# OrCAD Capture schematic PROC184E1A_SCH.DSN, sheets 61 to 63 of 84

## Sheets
61 64. DSI to eDP bridge: size C; title: DSI TO EDP BRIDGE; note: PROC184_SCH
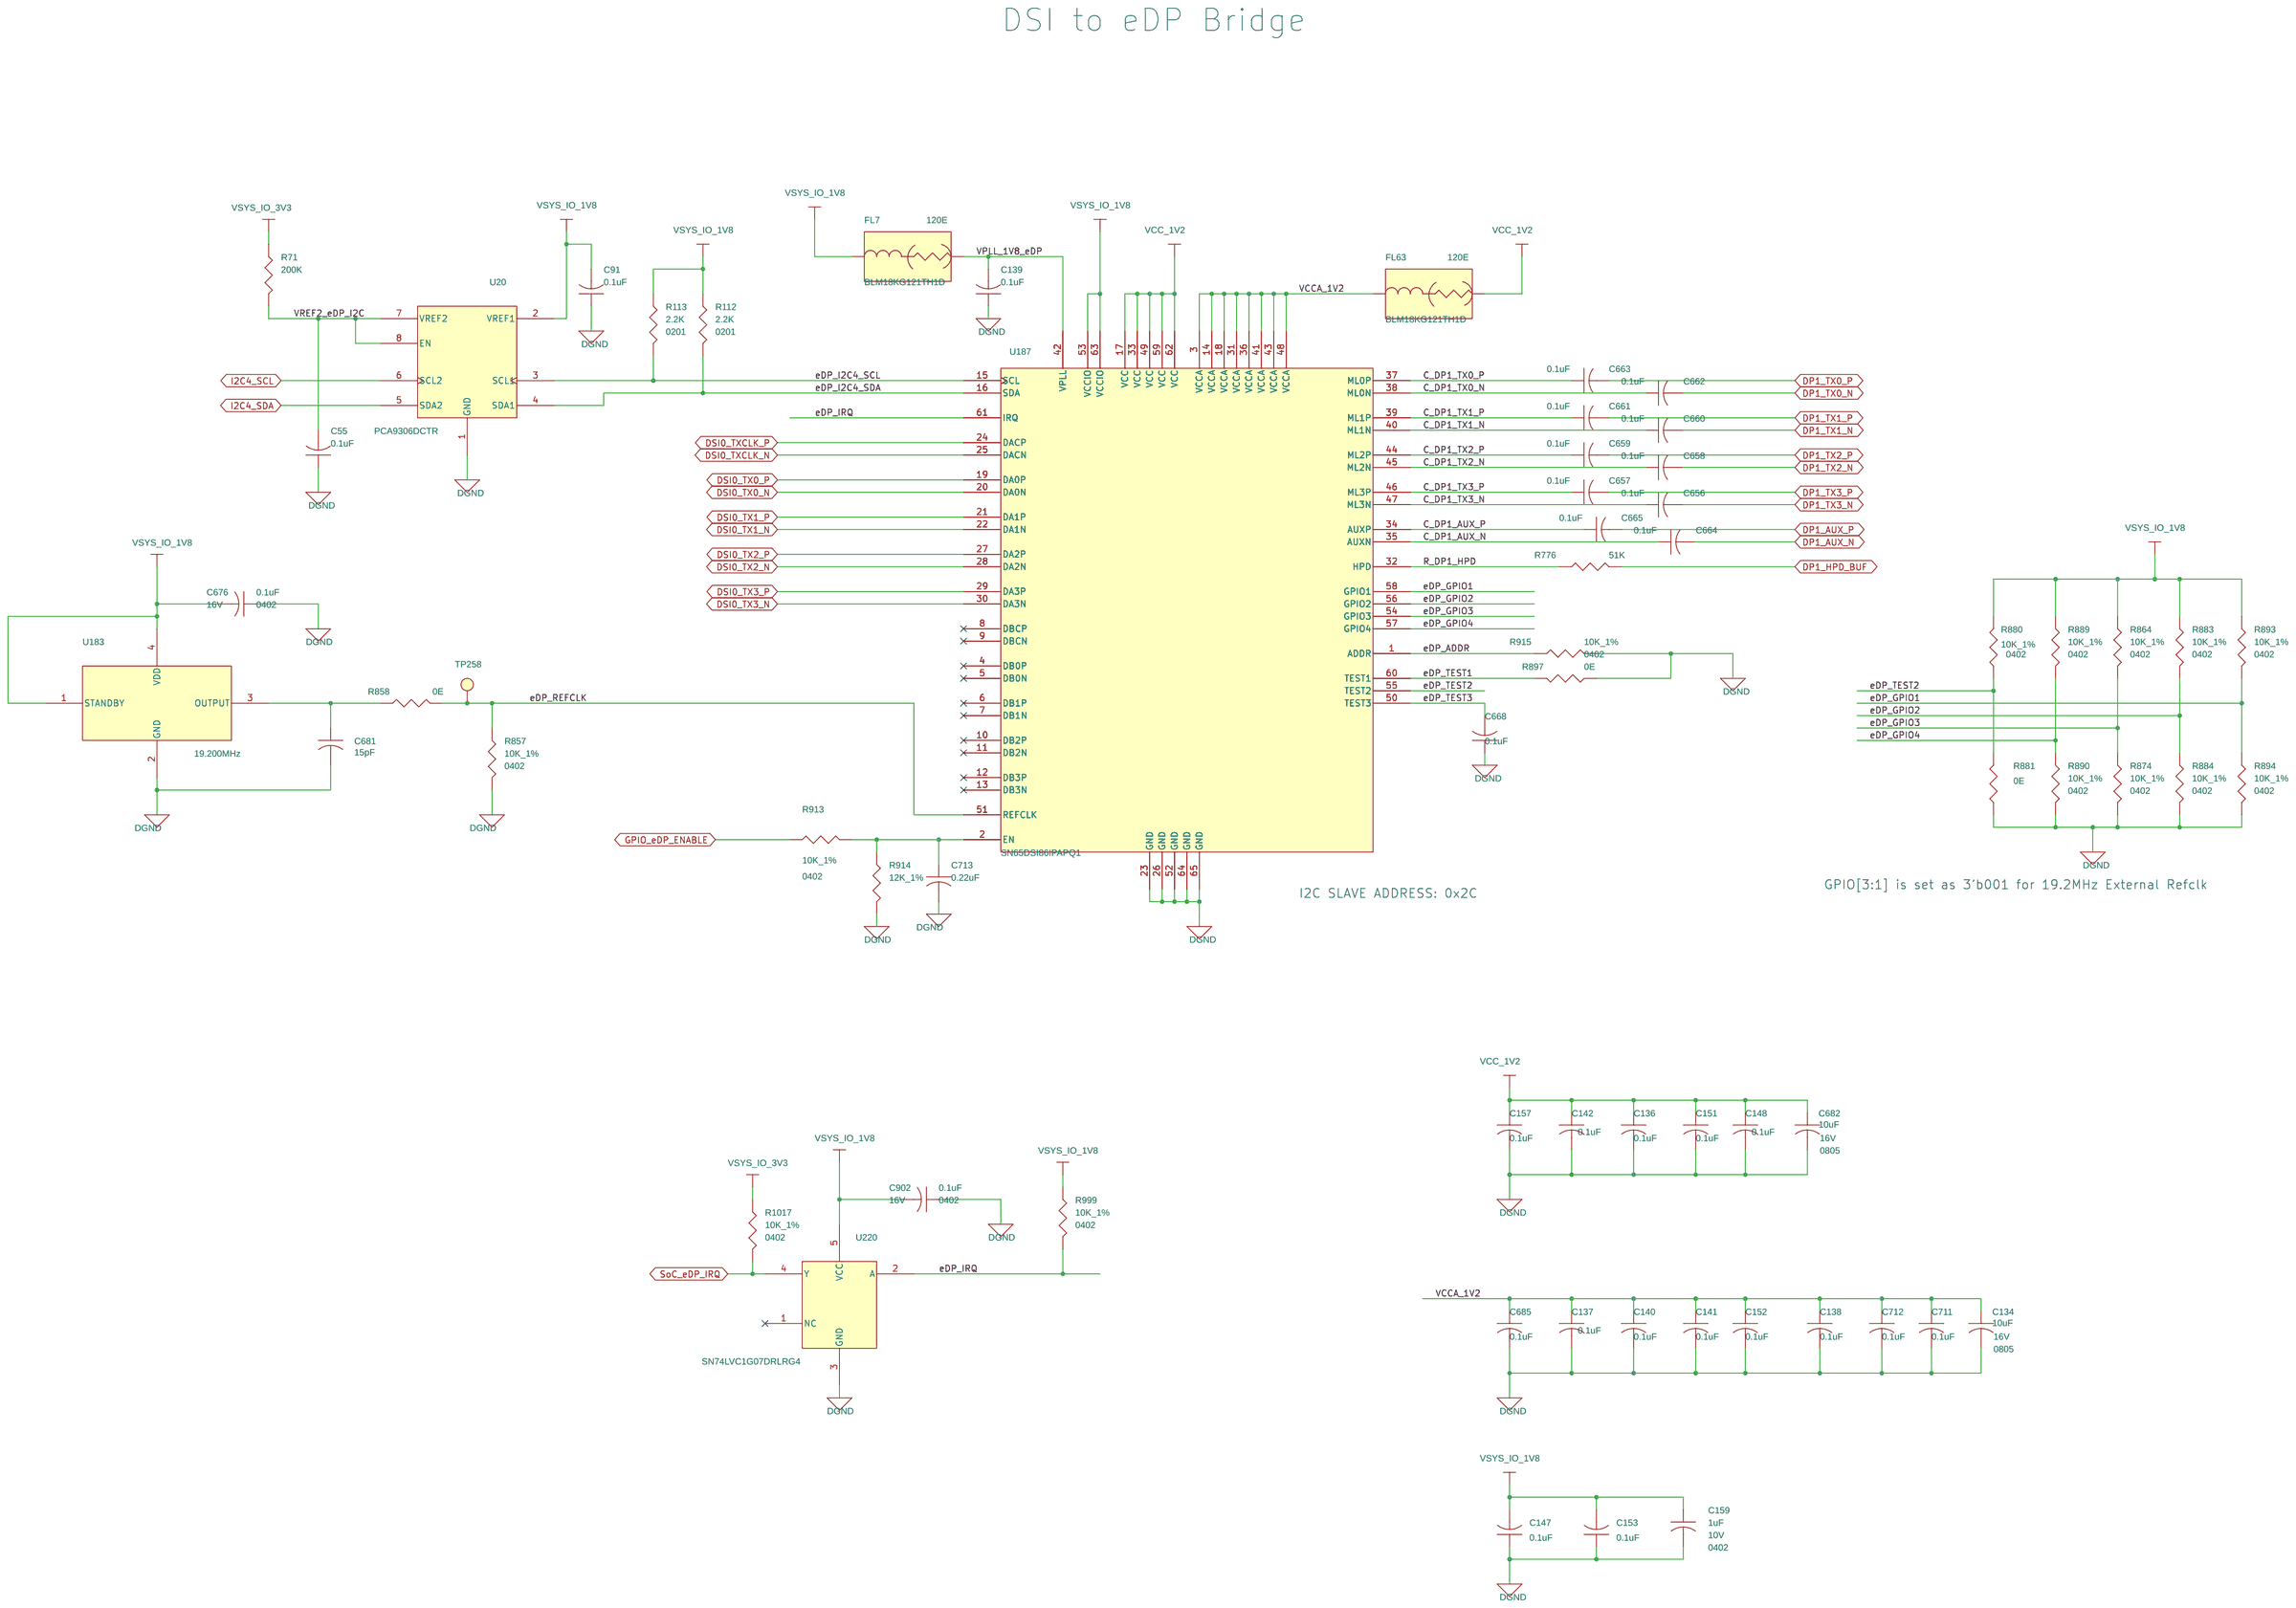
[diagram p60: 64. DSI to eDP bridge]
62 69. BOOT MODE BUFFER & SWITCHES: size C; title: BOOT MODE BUFFER & SWITCHES; note: PROC184_SCH
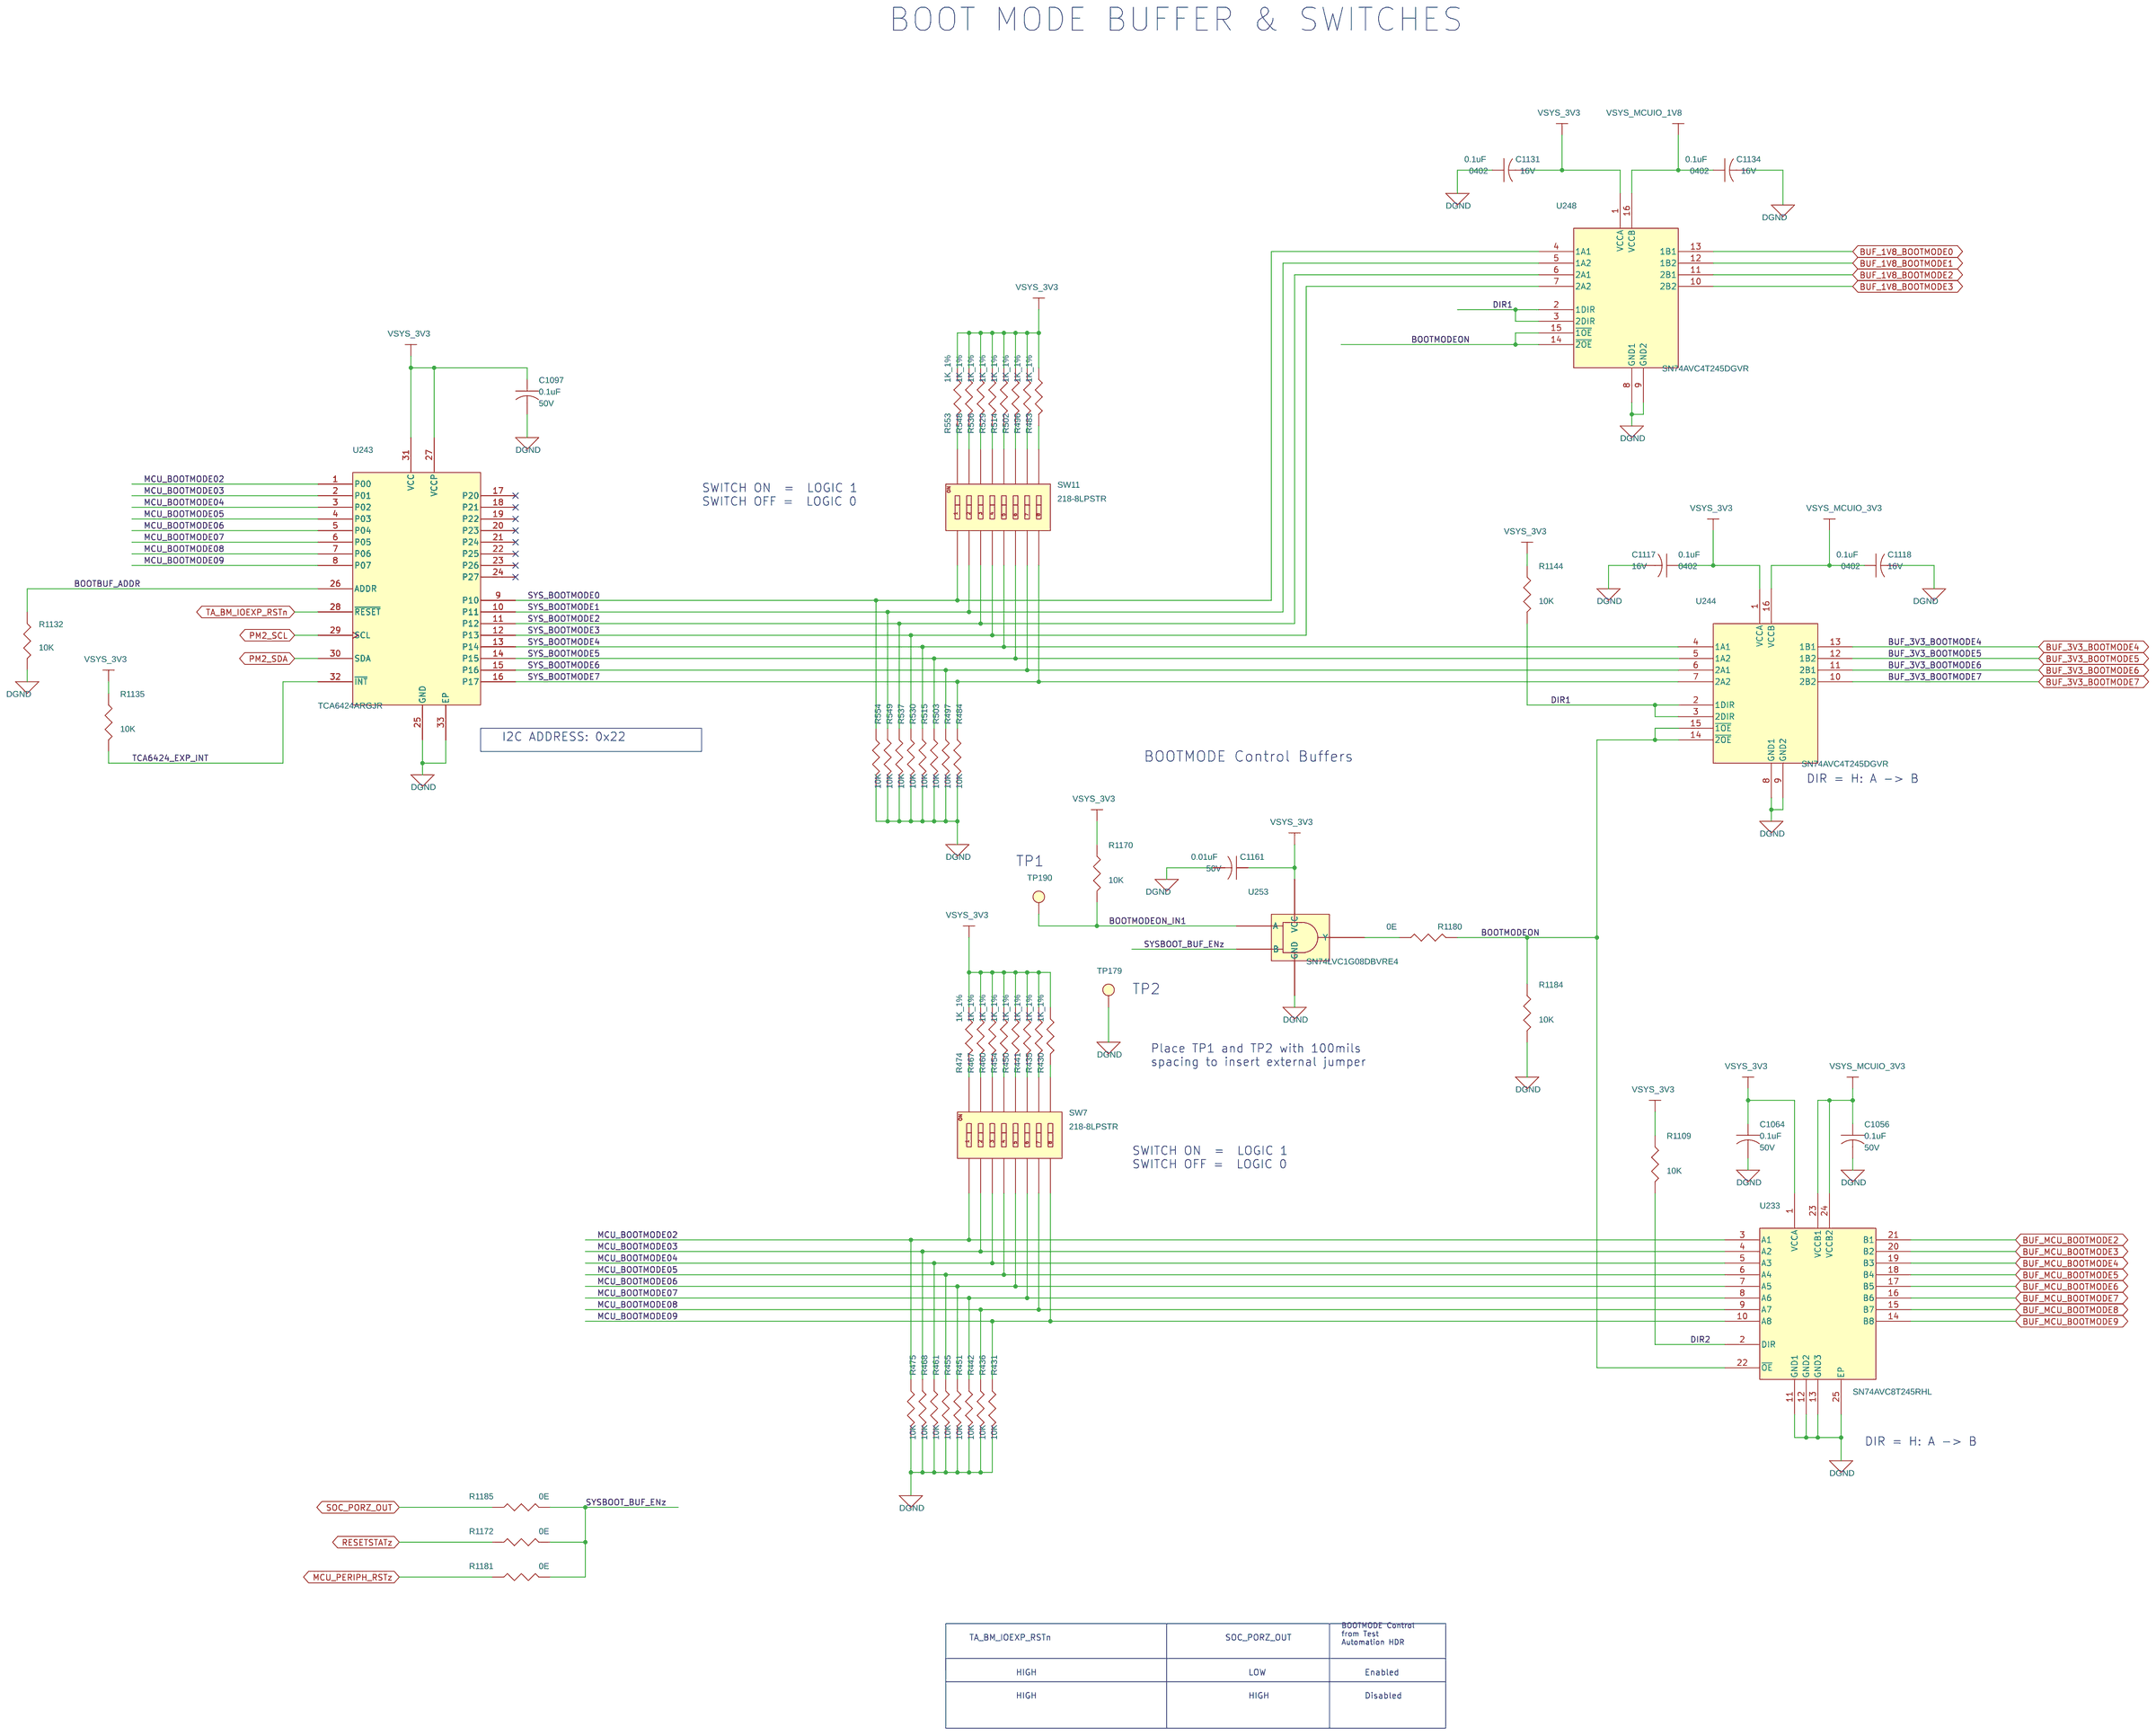
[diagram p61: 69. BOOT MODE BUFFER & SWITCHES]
63 70. TEST AUTOMATION HEADER: size C; title: TEST AUTOMATION HEADER; note: PROC184_SCH
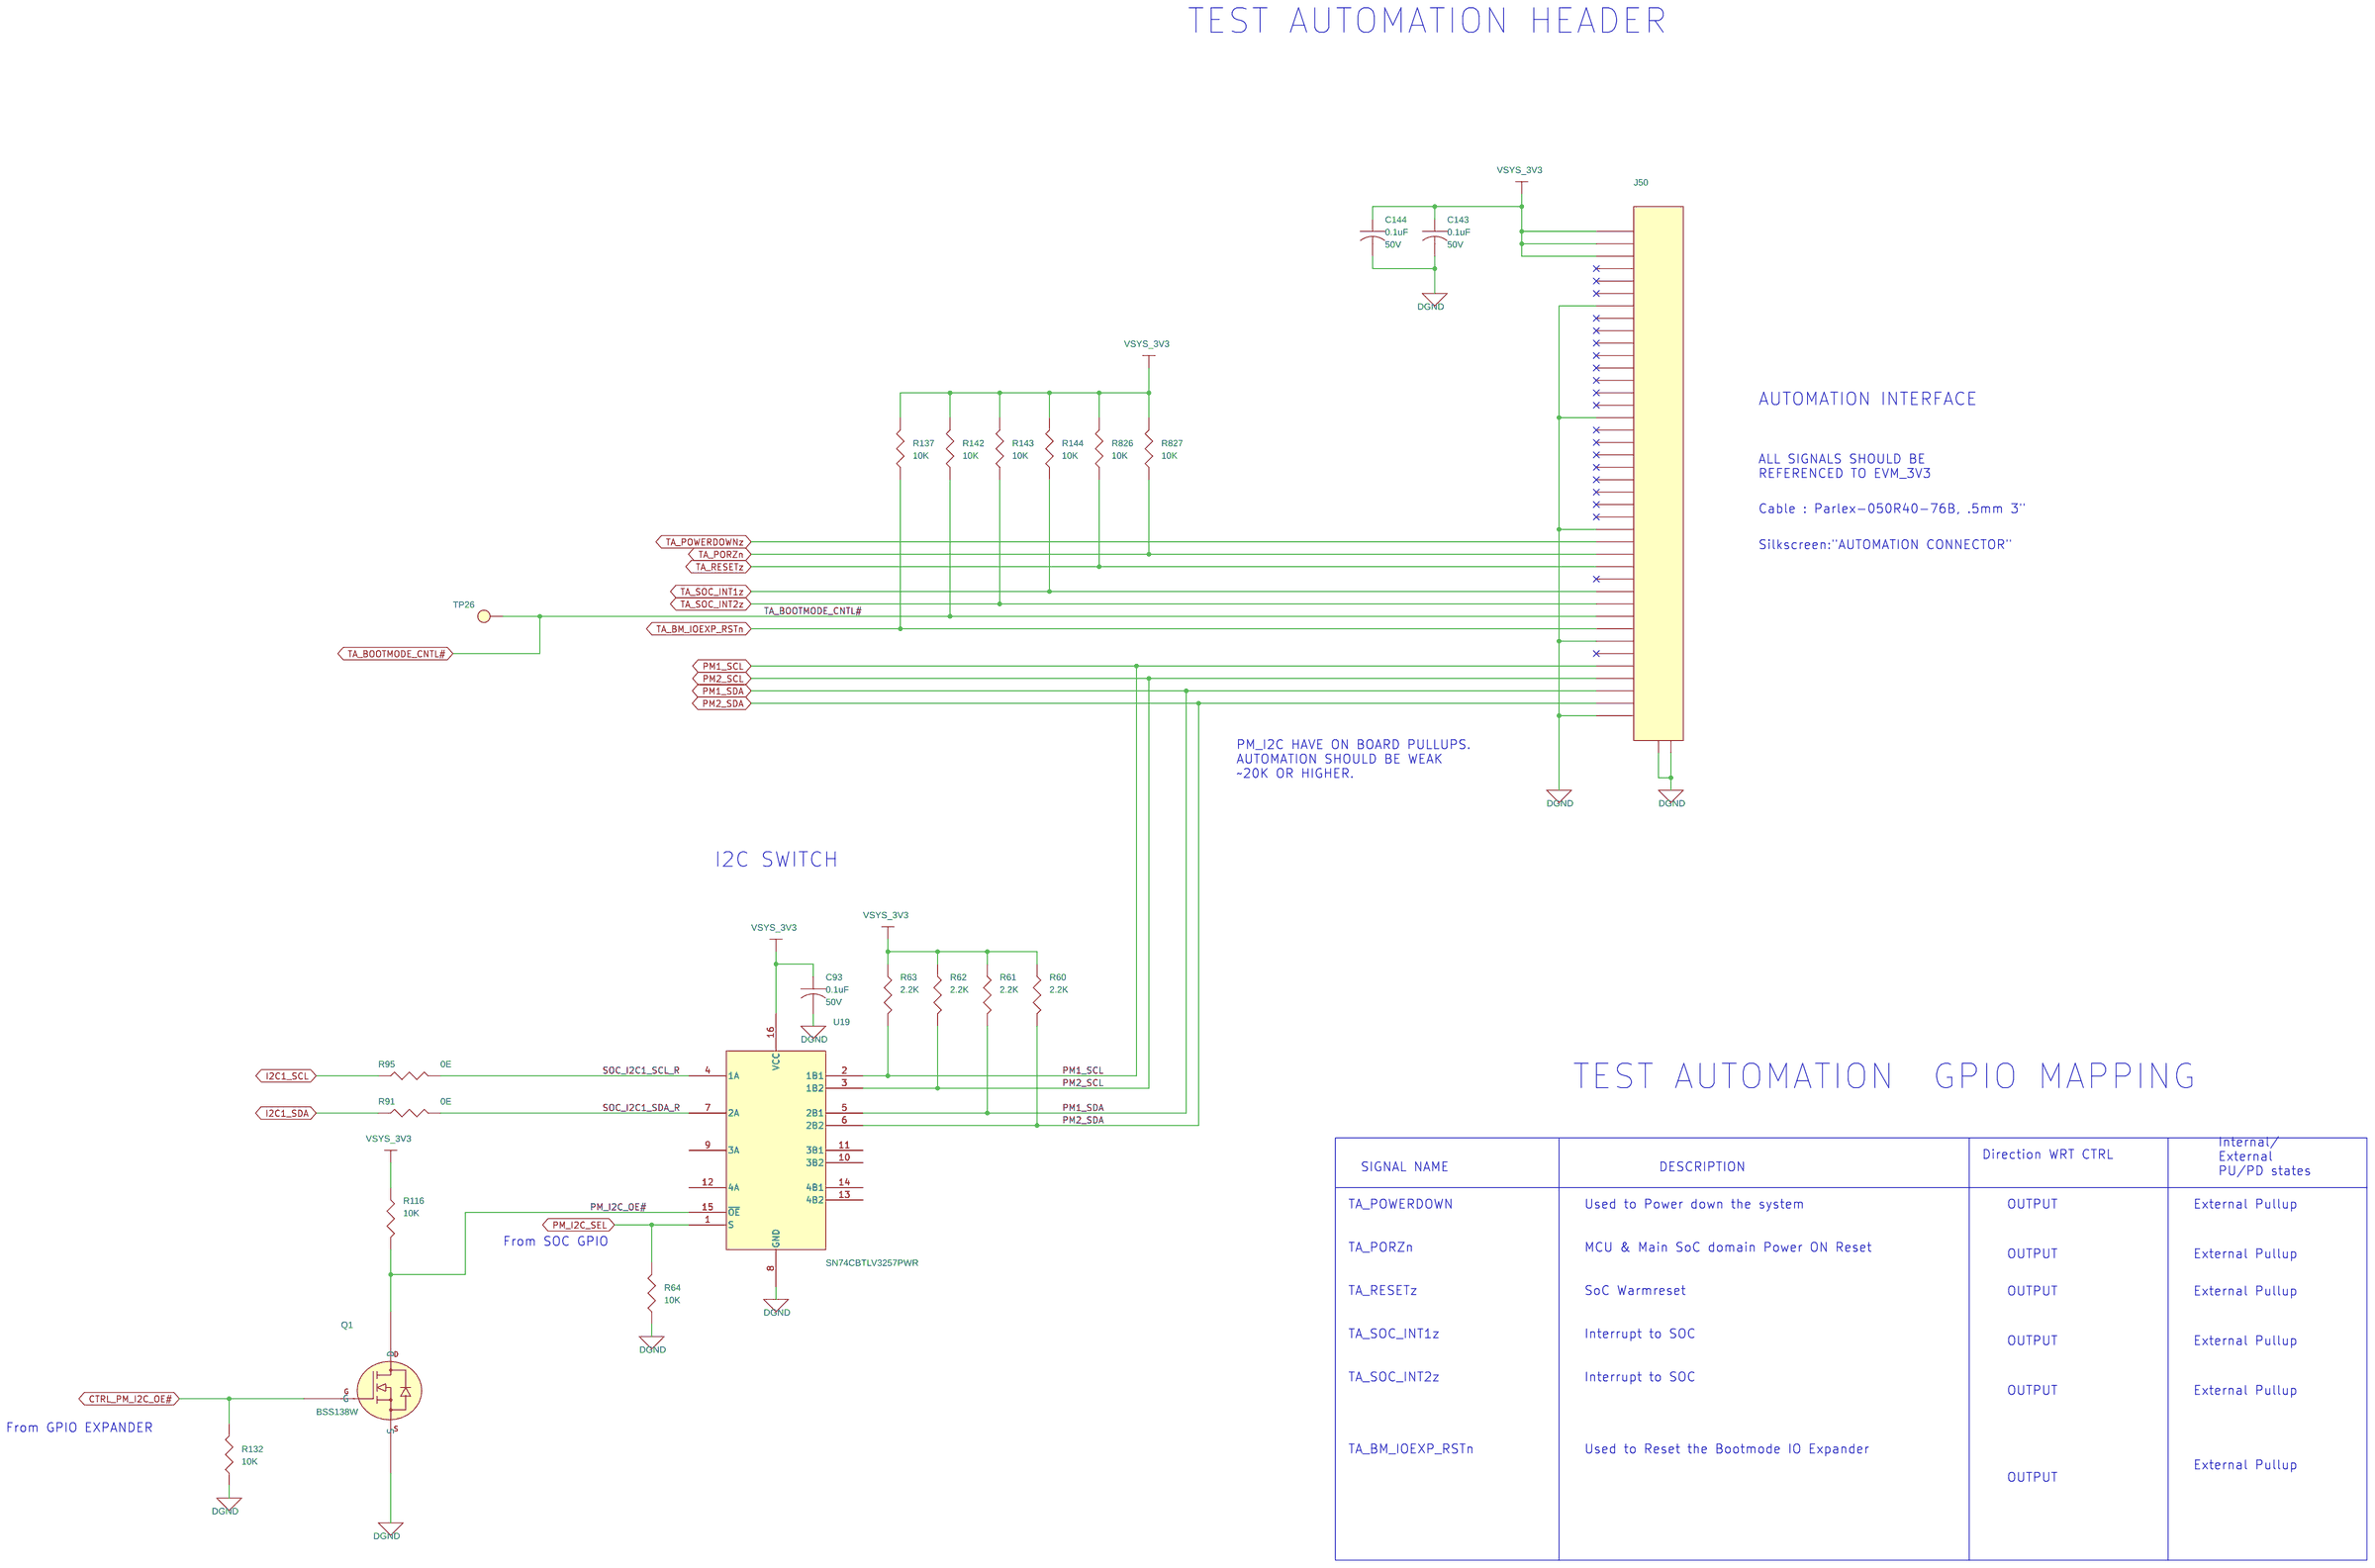
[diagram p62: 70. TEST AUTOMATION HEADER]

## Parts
sheet 64. DSI to eDP bridge
C55  0.1uF  [CAP0402_0-75]
C91  0.1uF  [CAP0402_0-75]
C134  10uF  [CAP0805_1-5]
C136  0.1uF  [CAP0402_0-75]
C137  0.1uF  [CAP0402_0-75]
C138  0.1uF  [CAP0402_0-75]
C139  0.1uF  [CAP0402_0-75]
C140  0.1uF  [CAP0402_0-75]
C141  0.1uF  [CAP0402_0-75]
C142  0.1uF  [CAP0402_0-75]
C147  0.1uF  [CAP0402_0-75]
C148  0.1uF  [CAP0402_0-75]
C151  0.1uF  [CAP0402_0-75]
C152  0.1uF  [CAP0402_0-75]
C153  0.1uF  [CAP0402_0-75]
C157  0.1uF  [CAP0402_0-75]
C159  1uF  [CAP0402_0-75]
C656  0.1uF  [CAP0201_0-5]
C657  0.1uF  [CAP0201_0-5]
C658  0.1uF  [CAP0201_0-5]
C659  0.1uF  [CAP0201_0-5]
C660  0.1uF  [CAP0201_0-5]
C661  0.1uF  [CAP0201_0-5]
C662  0.1uF  [CAP0201_0-5]
C663  0.1uF  [CAP0201_0-5]
C664  0.1uF  [CAP0201_0-5]
C665  0.1uF  [CAP0201_0-5]
C668  0.1uF  [CAP0402_0-75]
C676  0.1uF  [CAP0402_0-75]
C681  15pF  [CAP0402_0-75]
C682  10uF  [CAP0805_1-5]
C685  0.1uF  [CAP0402_0-75]
C711  0.1uF  [CAP0402_0-75]
C712  0.1uF  [CAP0402_0-75]
C713  0.22uF  [CAP0201_0-5]
C902  0.1uF  [CAP0402_0-75]
FL7  120E  [EMIFIL_BLM18P_0603_0-8]
FL63  120E  [EMIFIL_BLM18P_0603_0-8]
R71  200K  [RES0402_0-5]
R112  2.2K  [RES0201_0-5]
R113  2.2K  [RES0201_0-5]
R776  51K  [RES0402_0-5]
R857  10K_1%  [RES0402_0-5]
R858  0E  [RES0402_0-5]
R864  10K_1%  [RES0402_0-5]
R874  10K_1%  [RES0402_0-5]
R880  10K_1%  [RES0402_0-5]
R881  0E  [RES0402_0-5]
R883  10K_1%  [RES0402_0-5]
R884  10K_1%  [RES0402_0-5]
R889  10K_1%  [RES0402_0-5]
R890  10K_1%  [RES0402_0-5]
R893  10K_1%  [RES0402_0-5]
R894  10K_1%  [RES0402_0-5]
R897  0E  [RES0402_0-5]
R913  10K_1%  [RES0402_0-5]
R914  12K_1%  [RES0402_0-5]
R915  10K_1%  [RES0402_0-5]
R999  10K_1%  [RES0402_0-5]
R1017  10K_1%  [RES0402_0-5]
TP258  TP30_SMD  [TP30_SMD]
U20  PCA9306DCTR  [SSOP8_25-59_120X110_1-3]
U183  19.200MHz  [OSC4_831056216_80X70_SMD_0-8]
U187  SN65DSI86IPAPQ1  [HTQFP64_SN65DSI86_400X400_1-2]
U220  SN74LVC1G07DRLRG4  [SOT553-5_0-6]
sheet 69. BOOT MODE BUFFER & SWITCHES
C1056  0.1uF  [CAP0402_0-75]
C1064  0.1uF  [CAP0402_0-75]
C1097  0.1uF  [CAP0402_0-75]
C1117  0.1uF  [CAP0402_0-75]
C1118  0.1uF  [CAP0402_0-75]
C1131  0.1uF  [CAP0402_0-75]
C1134  0.1uF  [CAP0402_0-75]
C1161  0.01uF  [CAP0402_0-75]
R430  1K_1%  [RES0402_0-5]
R431  10K  [RES0402_0-5]
R435  1K_1%  [RES0402_0-5]
R436  10K  [RES0402_0-5]
R441  1K_1%  [RES0402_0-5]
R442  10K  [RES0402_0-5]
R450  1K_1%  [RES0402_0-5]
R451  10K  [RES0402_0-5]
R454  1K_1%  [RES0402_0-5]
R455  10K  [RES0402_0-5]
R460  1K_1%  [RES0402_0-5]
R461  10K  [RES0402_0-5]
R467  1K_1%  [RES0402_0-5]
R468  10K  [RES0402_0-5]
R474  1K_1%  [RES0402_0-5]
R475  10K  [RES0402_0-5]
R483  1K_1%  [RES0402_0-5]
R484  10K  [RES0402_0-5]
R496  1K_1%  [RES0402_0-5]
R497  10K  [RES0402_0-5]
R502  1K_1%  [RES0402_0-5]
R503  10K  [RES0402_0-5]
R514  1K_1%  [RES0402_0-5]
R515  10K  [RES0402_0-5]
R529  1K_1%  [RES0402_0-5]
R530  10K  [RES0402_0-5]
R536  1K_1%  [RES0402_0-5]
R537  10K  [RES0402_0-5]
R548  1K_1%  [RES0402_0-5]
R549  10K  [RES0402_0-5]
R553  1K_1%  [RES0402_0-5]
R554  10K  [RES0402_0-5]
R1109  10K  [RES0402_0-5]
R1132  10K  [RES0402_0-5]
R1135  10K  [RES0402_0-5]
R1144  10K  [RES0402_0-5]
R1170  10K  [RES0402_0-5]
R1172  0E  [RES0402_0-5]
R1180  0E  [RES0402_0-5]
R1181  0E  [RES0402_0-5]
R1184  10K  [RES0402_0-5]
R1185  0E  [RES0402_0-5]
SW7  218-8LPSTR  [SW8_218-8LPST_450X230_SMD_2-7]
SW11  218-8LPSTR  [SW8_218-8LPST_450X230_SMD_2-7]
TP179  THRU HOLE  [TP_40X65]
TP190  THRU HOLE  [TP_40X65]
U233  SN74AVC8T245RHL  [QFN24_19-68_220X140_1]
U243  TCA6424ARGJR  [QFN32_19-68_200X200]
U244  SN74AVC4T245DGVR  [TVSOP16_15-74_150X180]
U248  SN74AVC4T245DGVR  [TVSOP16_15-74_150X180]
U253  SN74LVC1G08DBVRE4  [SOT23-5]
sheet 70. TEST AUTOMATION HEADER
C93  0.1uF  [CAP0402_0-75]
C143  0.1uF  [CAP0402_0-75]
C144  0.1uF  [CAP0402_0-75]
J50  CON_FLEX_40X1_FH12A-40S-0.5SH  [CON_FLEX40X1_FH12A_S_R_S]
Q1  BSS138W  [TO_SOT323-123]
R60  2.2K  [RES0402_0-5]
R61  2.2K  [RES0402_0-5]
R62  2.2K  [RES0402_0-5]
R63  2.2K  [RES0402_0-5]
R64  10K  [RES0402_0-5]
R91  0E  [RES0402_0-5]
R95  0E  [RES0402_0-5]
R116  10K  [RES0402_0-5]
R132  10K  [RES0402_0-5]
R137  10K  [RES0402_0-5]
R142  10K  [RES0402_0-5]
R143  10K  [RES0402_0-5]
R144  10K  [RES0402_0-5]
R826  10K  [RES0402_0-5]
R827  10K  [RES0402_0-5]
TP26  TP40_SMD  [TP40_SMD]
U19  SN74CBTLV3257PWR  [TSSOP16_25-59_205X180]

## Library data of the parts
C55 C91 C136-C142 C147 C148 C151-C153 C157 C668 C676 C685 C711 C712 C902 C1117 C1118 C1131 C1134 = CAP: CAP CERAMIC 0.1uF 16V 10% X7R AUTO 0402; Automotive Alternate_mfr_name: TDK; Automotive Alternate_mfr_part_number: CGA2B1X7R1C104K050BC; Chkd/date: NAVEED/021014; Crtd /date: VASANTHA/300514; Custom_Duty: 15%; Customs_HS_Code: 85322990; Direct Alternate_mfr_name: MURATA; Direct Alternate_mfr_part_number: GCM155R71C104JA55D; Distributor_name: DIGIKEY; Distributor_part_number: 490-4759-1-ND; Footprint Path: Y:\MIS_DATABASE\Library\ALTIUM_TOOL\PCB_FOOTPRINTS\Altium_Footprint_Lib.PcbLib; Height: 0.55MM; Library Path: Y:\MIS_DATABASE\Library\ALTIUM_TOOL\SCHEMATICS_PARTS\MS_DISCRETE_Library.schlib; Manufacturer: MURATA; Mfr_name: MURATA; Mfr_part_number: GCM155R71C104KA55D; Mistral Part No: 120016070006-R; Package: 0402; Part_type: CAPACITORS\CERAMIC; Project: DCMIST_FPGA_CARD; RoHS: RoHS; Temperature: -55°C+125°C; Tolerance: 10%; Voltage: 16V; Wattage: NA; Weight: 6mg; Datasheet: Y:\MIS_DATABASE\DATASHEETS\CAPACITORS\MURATA-GCM-SER.PDF
C134 C682 = CAP: CAP CERAMIC 10uF 16V 10% X5R 0805; Automotive Alternate_mfr_name: MURATA; Automotive Alternate_mfr_part_number: GCM21BR71A106KE22L; Chkd/date: SHREESHAIL/220506; Crtd /date: MAZHAR/150506; Custom_Duty: 15%; Customs_HS_Code: 85322990; Direct Alternate_mfr_name: SAMSUNG; Direct Alternate_mfr_part_number: CL21B106KPQNNNE; Distributor_name: DIGIKEY; Distributor_part_number: 490-3886-1-ND; Footprint Path: Y:\MIS_DATABASE\Library\ALTIUM_TOOL\PCB_FOOTPRINTS\Altium_Footprint_Lib.PcbLib; Height: 1.35MM; Library Path: Y:\MIS_DATABASE\Library\ALTIUM_TOOL\SCHEMATICS_PARTS\MS_DISCRETE_Library.schlib; Manufacturer: MURATA; Mfr_name: MURATA; Mfr_part_number: GRM21BR61C106KE15L; Mistral Part No: 120009030205-R; Package: 0805; Part_type: CAPACITORS\CERAMIC; Project: VOCERA; RoHS: RoHS; Temperature: -55°C+85°C; Tolerance: 10%; Voltage: 16V; Wattage: NA; Weight: 9.5mg; Datasheet: Y:\MIS_DATABASE\DATASHEETS\CAPACITORS\MURATA-GXX-SER_NOV17.PDF
C159 = CAP: CAP CERAMIC 1uF 10V 10% X7S AUTO 0402; Chkd/date: MANIRAJA/100918; Crtd /date: ALVY/100918; Custom_Duty: 15%; Customs_HS_Code: 85322990; Distributor_name: DIGIKEY; Distributor_part_number: 490-13409-1-ND; Footprint Path: Y:\MIS_DATABASE\Library\ALTIUM_TOOL\PCB_FOOTPRINTS\Altium_Footprint_Lib.PcbLib; Height: 0.70MM; Library Path: Y:\MIS_DATABASE\Library\ALTIUM_TOOL\SCHEMATICS_PARTS\MS_DISCRETE_Library.schlib; Manufacturer: MURATA; Mfr_name: MURATA; Mfr_part_number: GCM155C71A105KE38D; Mistral Part No: 120018090021-R; Package: 0402; Part_type: CAPACITORS\CERAMIC; Project: SMART-M_SCRIPTALK_PB; RoHS: RoHS; Temperature: -55°C+125°C; Tolerance: 10%; Voltage: 10V; Wattage: NA; Weight: 6mg; Datasheet: Y:\MIS_DATABASE\DATASHEETS\CAPACITORS\MURATA-GCM-SER.PDF
C656-C665 = CAP: CAP CERAMIC 0.1uF 6.3V 10% X7S AUTO 0201; Chkd/date: MANIRAJA/011018; Crtd /date: MANIRAJA/011018; Custom_Duty: 15%; Customs_HS_Code: 85322990; Distributor_name: NA; Distributor_part_number: NA; Footprint Path: Y:\MIS_DATABASE\Library\ALTIUM_TOOL\PCB_FOOTPRINTS\Altium_Footprint_Lib.PcbLib; Height: 0.33MM; Library Path: Y:\MIS_DATABASE\Library\ALTIUM_TOOL\SCHEMATICS_PARTS\MS_DISCRETE_Library.schlib; Manufacturer: MURATA; Mfr_name: MURATA; Mfr_part_number: GCM033C70J104KE02D; Mistral Part No: 120018100001-R; Package: 0201; Part_type: CAPACITORS\CERAMIC; Project: TI_J7_SVB-DUT; RoHS: RoHS; Temperature: -55°C+125°C; Tolerance: 10%; Voltage: 6.3V; Wattage: NA; Weight: NA; Datasheet: Y:\MIS_DATABASE\DATASHEETS\CAPACITORS\MURATA-GCM-SER.PDF
C681 = CAP: CAP CERAMIC 15pF 50V 5% C0G(NP0) 0402; Automotive Alternate_mfr_name: TDK; Automotive Alternate_mfr_part_number: CGA2B2C0G1H150J050BA; Chkd/date: MANIRAJA/020419; Crtd /date: MANIRAJA/020419; Custom_Duty: 15%; Customs_HS_Code: 85322990; Direct Alternate_mfr_name: TDK; Direct Alternate_mfr_part_number: C1005NP01H150J050BA; Distributor_name: DIGIKEY; Distributor_part_number: 399-1014-1-ND; Footprint Path: Y:\MIS_DATABASE\Library\ALTIUM_TOOL\PCB_FOOTPRINTS\Altium_Footprint_Lib.PcbLib; Height: 0.55MM; Library Path: Y:\MIS_DATABASE\Library\ALTIUM_TOOL\SCHEMATICS_PARTS\MS_DISCRETE_Library.schlib; Manufacturer: KEMET; Mfr_name: KEMET; Mfr_part_number: C0402C150J5GACTU; Mistral Part No: 120009030233-R; Package: 0402; Part_type: CAPACITORS\CERAMIC; Project: VOCERA; RoHS: RoHS; Temperature: -55°C+125°C; Tolerance: 5%; Voltage: 50V; Wattage: NA; Weight: 0.65mg; Datasheet: Y:\MIS_DATABASE\DATASHEETS\CAPACITORS\KEMET-C0G_SERIES.PDF
C713 = CAP: CAP CERAMIC 0.22uF 6.3V 10% X6S AUTO 0201; Chkd/date: MANIRAJA/220219; Crtd /date: ALVY/220219; Custom_Duty: 15%; Customs_HS_Code: 85322990; Distributor_name: DIGIKEY; Distributor_part_number: 490-12230-1-ND; Footprint Path: Y:\MIS_DATABASE\Library\ALTIUM_TOOL\PCB_FOOTPRINTS\Altium_Footprint_Lib.PcbLib; Height: 0.33MM; Library Path: Y:\MIS_DATABASE\Library\ALTIUM_TOOL\SCHEMATICS_PARTS\MS_DISCRETE_Library.schlib; Manufacturer: MURATA; Mfr_name: MURATA; Mfr_part_number: GRT033C80J224KE01D; Mistral Part No: 120019020011-R; Package: 0201; Part_type: CAPACITORS\CERAMIC; Project: TI_J7ES_EVM_SOM; RoHS: RoHS; Temperature: -55°C+105°C; Tolerance: 10%; Voltage: 6.3V; Wattage: NA; Weight: 0.17mg; Datasheet: Y:\MIS_DATABASE\DATASHEETS\CAPACITORS\MURATA-GCM-SER.PDF
FL7 FL63 = EMIFILTER_IND: IND FERRITE BEAD CHIP 120E 3A 0603; Automotive Alternate_mfr_name: TDK; Automotive Alternate_mfr_part_number: MPZ1608S121ATDH5; Chkd/date: MANIRAJA/251018; Crtd /date: ALVY/251018; Custom_Duty: 24%; Customs_HS_Code: 85437099; Direct Alternate_mfr_name: TDK; Direct Alternate_mfr_part_number: MPZ1608S121ATAH0; Distributor_name: DIGIKEY; Distributor_part_number: 490-13261-1-ND; Footprint Path: Y:\MIS_DATABASE\Library\ALTIUM_TOOL\PCB_FOOTPRINTS\Altium_Footprint_Lib.PcbLib; Height: 0.75MM; Library Path: Y:\MIS_DATABASE\Library\ALTIUM_TOOL\SCHEMATICS_PARTS\MS_FILTER_Library.schlib; Manufacturer: MURATA; Mfr_name: MURATA; Mfr_part_number: BLM18KG121TH1D; Mistral Part No: 130018100051-R; Package: 0603; Part_type: INDUCTOR; Project: TI_J7ES_EVM_SOM; RoHS: RoHS; Temperature: -55°C+125°C; Tolerance: 25%; Voltage: NA; Wattage: NA; Weight: 4mg; Datasheet: Y:\MIS_DATABASE\DATASHEETS\DISCRETES\INDUCTORS\BLM18XX-H1D-SER.PDF
R71 = RESISTOR: RES 200K 1/10W 5% 0402; Chkd/date: MANOJ/230414; Crtd /date: USMAN/151013; Custom_Duty: 15%; Customs_HS_Code: 85332119; Distributor_name: DIGIKEY; Distributor_part_number: P200KJCT-ND; Footprint Path: Y:\MIS_DATABASE\Library\ALTIUM_TOOL\PCB_FOOTPRINTS\Altium_Footprint_Lib.PcbLib; Height: 0.40MM; Library Path: Y:\MIS_DATABASE\Library\ALTIUM_TOOL\SCHEMATICS_PARTS\MS_DISCRETE_Library.schlib; Manufacturer: PANASONIC-ECG; Mfr_name: PANASONIC-ECG; Mfr_part_number: ERJ-2GEJ204X; Mistral Part No: 110013100006-R; Package: 0402; Part_type: RESISTORS\FIXED; Project: C-BAND_SYNTH; RoHS: RoHS; Temperature: -55°C+155°C; Tolerance: 5%; Voltage: NA; Wattage: 1/10W; Weight: 0.8mg; Datasheet: Y:\MIS_DATABASE\DATASHEETS\RESISTORS\PAN-ERJSER_NOV17.PDF
R112 R113 = RESISTOR: RES 2.2K 1/20W 5% 0201; Chkd/date: MANIRAJA/050517; Crtd /date: MANIRAJA/050517; Custom_Duty: 15%; Customs_HS_Code: 85332119; Distributor_name: DIGIKEY; Distributor_part_number: 311-2.2KNCT-ND; Footprint Path: Y:\MIS_DATABASE\Library\ALTIUM_TOOL\PCB_FOOTPRINTS\Altium_Footprint_Lib.PcbLib; Height: 0.26MM; Library Path: Y:\MIS_DATABASE\Library\ALTIUM_TOOL\SCHEMATICS_PARTS\MS_DISCRETE_Library.schlib; Manufacturer: YAGEO AMERICA; Mfr_name: YAGEO AMERICA; Mfr_part_number: RC0201JR-072K2L; Mistral Part No: 110009030427-R; Package: 0201; Part_type: RESISTORS\FIXED; Project: GOLDEN-I LITE; RoHS: RoHS; Temperature: -55°C+125°C; Tolerance: 5%; Voltage: NA; Wattage: 1/20W; Weight: 0.17mg; Datasheet: Y:\MIS_DATABASE\DATASHEETS\RESISTORS\RCXXXXL-SER_MAR18.PDF
R776 = RESISTOR: RES 51K 1/16W 5% 0402; Chkd/date: MANIRAJA/230817; Crtd /date: MANIRAJA/230817; Custom_Duty: 15%; Customs_HS_Code: 85332119; Distributor_name: DIGIKEY; Distributor_part_number: 541-51KJCT-ND; Footprint Path: Y:\MIS_DATABASE\Library\ALTIUM_TOOL\PCB_FOOTPRINTS\Altium_Footprint_Lib.PcbLib; Height: 0.40MM; Library Path: Y:\MIS_DATABASE\Library\ALTIUM_TOOL\SCHEMATICS_PARTS\MS_DISCRETE_Library.schlib; Manufacturer: VISHAY; Mfr_name: VISHAY; Mfr_part_number: CRCW040251K0JNED; Mistral Part No: 110009030966-R; Package: 0402; Part_type: RESISTORS\FIXED; Project: TI_MAXIE_CPB; RoHS: RoHS; Temperature: -55°C+155°C; Tolerance: 5%; Voltage: NA; Wattage: 1/16W; Weight: 0.65mg; Datasheet: Y:\MIS_DATABASE\DATASHEETS\RESISTORS\CRCW0603.PDF
R857 R864 R874 R880 R883 R884 R889 R890 R893 R894 R913 R915 R999 R1017 = RESISTOR: RES 10K 1/16W 1% 0402; Chkd/date: VASANTHA/201216; Crtd /date: GEETHA/290506; Custom_Duty: 15%; Customs_HS_Code: 85332119; Distributor_name: DIGIKEY; Distributor_part_number: 311-10.0KLRTR-ND; Footprint Path: Y:\MIS_DATABASE\Library\ALTIUM_TOOL\PCB_FOOTPRINTS\Altium_Footprint_Lib.PcbLib; Height: 0.40MM; Library Path: Y:\MIS_DATABASE\Library\ALTIUM_TOOL\SCHEMATICS_PARTS\MS_DISCRETE_Library.schlib; Manufacturer: YAGEO AMERICA; Mfr_name: YAGEO AMERICA; Mfr_part_number: RC0402FR-0710KL; Mistral Part No: 110015090015-R; Package: 0402; Part_type: RESISTORS\FIXED; Project: VOCERA; RoHS: RoHS; Temperature: -55°C+155°C; Tolerance: 1%; Voltage: NA; Wattage: 1/16W; Weight: 0.65mg; Datasheet: Y:\MIS_DATABASE\DATASHEETS\RESISTORS\RCXXXXL-SER_MAR18.PDF
R91 R95 R858 R881 R897 R1180 R1185 = RESISTOR: RES 0E 1/10W JUMPER 0402; Chkd/date: VASANTHA/061216; Crtd /date: NAVEED/201014; Custom_Duty: 15%; Customs_HS_Code: 85332119; Distributor_name: DIGIKEY; Distributor_part_number: P0.0JCT-ND; Footprint Path: Y:\MIS_DATABASE\Library\ALTIUM_TOOL\PCB_FOOTPRINTS\Altium_Footprint_Lib.PcbLib; Height: 0.40MM; IBISSP_MODLES: VALUE REPEATING 2 TIME; Library Path: Y:\MIS_DATABASE\Library\ALTIUM_TOOL\SCHEMATICS_PARTS\MS_DISCRETE_Library.schlib; Manufacturer: PANASONIC-ECG; Mfr_name: PANASONIC-ECG; Mfr_part_number: ERJ-2GE0R00X; Mistral Part No: 110018030052-R; Package: 0402; Part_type: RESISTORS\FIXED; Project: AEGIS POM; RoHS: RoHS; Temperature: -55°C+155°C; Tolerance: NA; Voltage: NA; Wattage: 1/10W; Weight: 0.8mg; Datasheet: Y:\MIS_DATABASE\DATASHEETS\RESISTORS\PAN-ERJSER_NOV17.PDF
R914 = RESISTOR: RES 12K 1/10W 1% 0402; Chkd/date: VASANTHA/041215; Crtd /date: VASANTHA/041215; Custom_Duty: 15%; Customs_HS_Code: 85332119; Distributor_name: DIGIKEY; Distributor_part_number: P12.0KLCT-ND; Footprint Path: Y:\MIS_DATABASE\Library\ALTIUM_TOOL\PCB_FOOTPRINTS\Altium_Footprint_Lib.PcbLib; Height: 0.40MM; Library Path: Y:\MIS_DATABASE\Library\ALTIUM_TOOL\SCHEMATICS_PARTS\MS_DISCRETE_Library.schlib; Manufacturer: PANASONIC-ECG; Mfr_name: PANASONIC-ECG; Mfr_part_number: ERJ-2RKF1202X; Mistral Part No: 110019040053-R; Package: 0402; Part_type: RESISTORS\FIXED; Project: TI_C5545; RoHS: RoHS; Temperature: -55°C+155°C; Tolerance: 1%; Voltage: NA; Wattage: 1/10W; Weight: 0.8mg; Datasheet: Y:\MIS_DATABASE\DATASHEETS\RESISTORS\PAN-ERJSER_NOV17.PDF
TP258 = TESTPOINT: TESTPOINT CIR 30 SMD; Chkd/date: SHREESHAIL/171006; Crtd /date: MAZHAR/171006; Custom_Duty: NA; Customs_HS_Code: NA; Distributor_name: NA; Distributor_part_number: NA; Footprint Path: Y:\MIS_DATABASE\Library\ALTIUM_TOOL\PCB_FOOTPRINTS\Altium_Footprint_Lib.PcbLib; Height: NA; Library Path: Y:\MIS_DATABASE\Library\ALTIUM_TOOL\SCHEMATICS_PARTS\MS_DISCRETE_Library.schlib; MECHANICAL 3D STEP FILE: NA; Manufacturer: LOCAL; Mfr_name: LOCAL; Mistral Part No: 130009030930; Package: SMD; Project: BT MODULE_CSRBC04; RoHS: NA; Temperature: NA; Tolerance: NA; Voltage: NA; Wattage: NA; Weight: NA; Datasheet: NA
U20 = PCA9306DCT_SSOP8: IC DUAL BI-DIR I2C BUS AND SMBUS VOLTAGE LEVEL TRANSLATOR SM8; Chkd/date: MAZHAR/231210; Crtd /date: BAVISH/221210; Custom_Duty: 15%; Customs_HS_Code: 85423100; Distributor_name: DIGIKEY; Distributor_part_number: 296-18509-1-ND; Footprint Path: Y:\MIS_DATABASE\Library\ALTIUM_TOOL\PCB_FOOTPRINTS\Altium_Footprint_Lib.PcbLib; Height: 1.30MM; Library Path: Y:\MIS_DATABASE\Library\ALTIUM_TOOL\SCHEMATICS_PARTS\MS_MISCINTERFACE_Library.schlib; Manufacturer: TEXAS INSTRUMENTS; Mfr_name: TEXAS INSTRUMENTS; Mistral Part No: 141010120015-R; Package: SM8; Part_type: ICS\INTERFACE\LEVEL TRANSLATOR; Project: CENTAURUS; RoHS: RoHS; Temperature: -40°C+85°C; Tolerance: NA; Voltage: NA; Wattage: NA; Weight: 59mg; Datasheet: Y:\MIS_DATABASE\DATASHEETS\ICS\INTERFACE\PCA9306XXX.PDF
U183 = OSC4_ASDMB: OSC 19.200MHz 1.8V CMOS SMD; Chkd/date: MANIRAJA/161221; Crtd /date: ALVY/161221; Custom_Duty: 24%; Customs_HS_Code: 85437099; Distributor_name: DIGIKEY; Distributor_part_number: 1923-830208217009CT-ND; Footprint Path: Y:\MIS_DATABASE\Library\ALTIUM_TOOL\PCB_FOOTPRINTS\Altium_Footprint_Lib.PcbLib; Height: 0.80MM; Library Path: Y:\MIS_DATABASE\Library\ALTIUM_TOOL\SCHEMATICS_PARTS\MS_DISCRETE_Library.schlib; Manufacturer: WURTH ELEKTRONIK; Mfr_name: WURTH ELEKTRONIK; Mfr_part_number: 830208217009; Mistral Part No: 130021120005-R; Package: SMD; Part_type: OSCILLATORS; Project: TI_J7AEP SOM_BRD; RoHS: RoHS; Temperature: -20°C+70°C; Tolerance: NA; Voltage: 1.8V; Wattage: NA; Weight: NA; Datasheet: Y:\MIS_DATABASE\DATASHEETS\MISC\CRY_OSC\830208217009.PDF
U187 = SN65DSI86-Q1_HTQFP64: IC MIPI DSI TO eDP BRIDGE HTQFP64; Chkd/date: MANIRAJA/090421; Crtd /date: ALVY/080421; Custom_Duty: 15%; Customs_HS_Code: 85423100; Distributor_name: DIGIKEY; Distributor_part_number: SN65DSI86IPAPQ1-ND; Footprint Path: Y:\MIS_DATABASE\Library\ALTIUM_TOOL\PCB_FOOTPRINTS\Altium_Footprint_Lib.PcbLib; Height: 1.20MM; Library Path: Y:\MIS_DATABASE\Library\ALTIUM_TOOL\SCHEMATICS_PARTS\MS_MISCINTERFACE_Library.schlib; Manufacturer: TEXAS INSTRUMENTS; Mfr_name: TEXAS INSTRUMENTS; Mistral Part No: 141021040001-R; Package: HTQFP64; Part_type: ICS\INTERFACE; Project: TI_J7AEP SOM BRD; RoHS: RoHS; Temperature: -40°C+85°C; Tolerance: NA; Voltage: NA; Wattage: NA; Weight: 306.5mg; Datasheet: Y:\MIS_DATABASE\DATASHEETS\ICS\INTERFACE\SN65DSI86-Q1.PDF
U220 = SN74LVC1G07DRLRG4_SOT553-5: IC SINGLE BUFFER/DRIVER WITH OPEN-DRAIN OUTPUT SOT553-5; Chkd/date: RAGESH/111110; Crtd /date: MAZHAR/170907; Custom_Duty: 15%; Customs_HS_Code: 85423100; Distributor_name: DIGIKEY; Distributor_part_number: SN74LVC1G07DRLRG4-ND; Footprint Path: Y:\MIS_DATABASE\Library\ALTIUM_TOOL\PCB_FOOTPRINTS\Altium_Footprint_Lib.PcbLib; Height: 0.60MM; Library Path: Y:\MIS_DATABASE\Library\ALTIUM_TOOL\SCHEMATICS_PARTS\MS_LINEDRIVERRECEIVER_Library.schlib; Manufacturer: TEXAS INSTRUMENTS; Mfr_name: TEXAS INSTRUMENTS; Mistral Part No: 141009030406-R; Package: SOT553-5; Part_type: ICS\INTERFACE\LINE DRIVER; Project: SMART VIEW_IP CAMERA; RoHS: RoHS; Temperature: -40°C+125°C; Tolerance: NA; Voltage: NA; Wattage: NA; Weight: 2.8mg; Datasheet: Y:\MIS_DATABASE\DATASHEETS\ICS\INTERFACE\SN74LVC1G07-SER.PDF
C93 C143 C144 C1056 C1064 C1097 = CAP: CAP CERAMIC 0.1uF 50V 10% X7R 0402; Automotive Alternate_mfr_name: TDK; Automotive Alternate_mfr_part_number: CGA2B3X7R1H104K050BB; Chkd/date: MANIRAJA/261020; Crtd /date: ALVY/211020; Custom_Duty: 15%; Customs_HS_Code: 85322990; Direct Alternate_mfr_name: TDK; Direct Alternate_mfr_part_number: C1005X7R1H104K050BE; Distributor_name: DIGIKEY; Distributor_part_number: 490-10700-1-ND; Footprint Path: Y:\MIS_DATABASE\Library\ALTIUM_TOOL\PCB_FOOTPRINTS\Altium_Footprint_Lib.PcbLib; Height: 0.55MM; Library Path: Y:\MIS_DATABASE\Library\ALTIUM_TOOL\SCHEMATICS_PARTS\MS_DISCRETE_Library.schlib; Manufacturer: MURATA; Mfr_name: MURATA; Mfr_part_number: GRM155R71H104KE14D; Mistral Part No: 120011100014-R; Package: 0402; Part_type: CAPACITORS\CERAMIC; Project: J7_CP; RoHS: RoHS; Temperature: -55°C+125°C; Tolerance: 10%; Voltage: 50V; Wattage: NA; Weight: 3.1mg; Datasheet: Y:\MIS_DATABASE\DATASHEETS\CAPACITORS\GRM155R71H104KE14.PDF
C1161 = CAP: CAP CERAMIC 0.01uF 50V 10% X7R 0402; Automotive Alternate_mfr_name: TDK; Automotive Alternate_mfr_part_number: CGA2B2X7R1E103K050BA; Chkd/date: MANIRAJA/280319; Crtd /date: MANIRAJA/280319; Custom_Duty: 15%; Customs_HS_Code: 85322990; Direct Alternate_mfr_name: YAGEO AMERICA; Direct Alternate_mfr_part_number: CC0402KRX7R8BB103; Distributor_name: DIGIKEY; Distributor_part_number: 490-4516-1-ND; Footprint Path: Y:\MIS_DATABASE\Library\ALTIUM_TOOL\PCB_FOOTPRINTS\Altium_Footprint_Lib.PcbLib; Height: 0.55MM; Library Path: Y:\MIS_DATABASE\Library\ALTIUM_TOOL\SCHEMATICS_PARTS\MS_DISCRETE_Library.schlib; Manufacturer: MURATA; Mfr_name: MURATA; Mfr_part_number: GRM155R71H103KA88D; Mistral Part No: 120009030025-R; Package: 0402; Part_type: CAPACITORS\CERAMIC; Project: G4_SVGA; RoHS: RoHS; Temperature: -55°C+125°C; Tolerance: 10%; Voltage: 50V; Wattage: NA; Weight: 0.65mg; Datasheet: Y:\MIS_DATABASE\DATASHEETS\CAPACITORS\GRM155R71H103KA88D.PDF
R430 R435 R441 R450 R454 R460 R467 R474 R483 R496 R502 R514 R529 R536 R548 R553 = RESISTOR: RES 1K 1/10W 1% 0402; Chkd/date: VASANTHA/281216; Crtd /date: MAZHAR/150506; Custom_Duty: 15%; Customs_HS_Code: 85332119; Distributor_name: DIGIKEY; Distributor_part_number: P1.00KLCT-ND; Footprint Path: Y:\MIS_DATABASE\Library\ALTIUM_TOOL\PCB_FOOTPRINTS\Altium_Footprint_Lib.PcbLib; Height: 0.40MM; Library Path: Y:\MIS_DATABASE\Library\ALTIUM_TOOL\SCHEMATICS_PARTS\MS_DISCRETE_Library.schlib; Manufacturer: PANASONIC-ECG; Mfr_name: PANASONIC-ECG; Mfr_part_number: ERJ-2RKF1001X; Mistral Part No: 110009030411-R; Package: 0402; Part_type: RESISTORS\FIXED; Project: VOCERA; RoHS: RoHS; Temperature: -55°C+155°C; Tolerance: 1%; Voltage: NA; Wattage: 1/10W; Weight: 0.8mg; Datasheet: Y:\MIS_DATABASE\DATASHEETS\RESISTORS\PAN-ERJSER_NOV17.PDF
R64 R116 R132 R137 R142-R144 R431 R436 R442 R451 R455 R461 R468 R475 R484 R497 R503 R515 R530 R537 R549 R554 R826 R827 R1109 R1132 R1135 R1144 R1170 R1184 = RESISTOR: RES 10K 1/16W 5% 0402; Chkd/date: VASANTHA/061216; Crtd /date: MAZHAR/230805; Custom_Duty: 15%; Customs_HS_Code: 85332119; Distributor_name: DIGIKEY; Distributor_part_number: 311-10KJRCT-ND; Footprint Path: Y:\MIS_DATABASE\Library\ALTIUM_TOOL\PCB_FOOTPRINTS\Altium_Footprint_Lib.PcbLib; Height: 0.40MM; Library Path: Y:\MIS_DATABASE\Library\ALTIUM_TOOL\SCHEMATICS_PARTS\MS_DISCRETE_Library.schlib; Manufacturer: YAGEO AMERICA; Mfr_name: YAGEO AMERICA; Mfr_part_number: RC0402JR-0710KL; Mistral Part No: 110011060021-R; Package: 0402; Part_type: RESISTORS\FIXED; Project: HSE; RoHS: RoHS; Temperature: -55°C+155°C; Tolerance: 5%; Voltage: NA; Wattage: 1/16W; Weight: 0.65mg; Datasheet: Y:\MIS_DATABASE\DATASHEETS\RESISTORS\RCXXXXL-SER_MAR18.PDF
R1172 R1181 = RESISTOR: RES 0E 1/10W JUMPER 0402; Assembly_Instruction: DNI; Chkd/date: VASANTHA/061216; Crtd /date: NAVEED/201014; Custom_Duty: 15%; Customs_HS_Code: 85332119; Distributor_name: DIGIKEY; Distributor_part_number: P0.0JCT-ND; Footprint Path: Y:\MIS_DATABASE\Library\ALTIUM_TOOL\PCB_FOOTPRINTS\Altium_Footprint_Lib.PcbLib; Height: 0.40MM; IBISSP_MODLES: VALUE REPEATING 2 TIME; Library Path: Y:\MIS_DATABASE\Library\ALTIUM_TOOL\SCHEMATICS_PARTS\MS_DISCRETE_Library.schlib; Manufacturer: PANASONIC-ECG; Mfr_name: PANASONIC-ECG; Mfr_part_number: ERJ-2GE0R00X; Mistral Part No: 110018030052-R; Package: 0402; Part_type: RESISTORS\FIXED; Project: AEGIS POM; RoHS: RoHS; Temperature: -55°C+155°C; Tolerance: NA; Voltage: NA; Wattage: 1/10W; Weight: 0.8mg; Datasheet: Y:\MIS_DATABASE\DATASHEETS\RESISTORS\PAN-ERJSER_NOV17.PDF
SW7 SW11 = SW8_218-8LPSTR: SWITCH DIP SPST HALF PITCH 8POS SMD; Chkd/date: MANIRAJA/230817; Crtd /date: MANIRAJA/230817; Custom_Duty: 24%; Customs_HS_Code: 85369090; Distributor_name: DIGIKEY; Distributor_part_number: CT3112CT-ND; Height: 2.65MM; Manufacturer: CTS; Mfr_name: CTS; Mistral Part No: 130017080019-R; Package: SMD; Part_type: ELECTRO-MECHANICAL\SWITCH; Project: TI_RF_DC CARD; RoHS: RoHS; Temperature: -55°C+85°C; Tolerance: NA; Voltage: NA; Wattage: NA; Weight: NA; Datasheet: Y:\MIS_DATABASE\DATASHEETS\MISC\SWITCHES\128-12LPST.PDF
TP179 TP190 = TESTPOINT: TESTPOINT 1.0MM DRILL PTH; Chkd/date: MAZHAR/271211; Crtd /date: SHREESHAIL/041005; Distributor_name: NA; Distributor_part_number: NA; Height: NA; Manufacturer: LOCAL; Mfr_name: LOCAL; Mistral Part No: 130009030938; Package: THRU-HOLE; Project: HSE; Datasheet: NA
U233 = SN74AVC8T245RHL_QFN24: IC BUS TRANSCEIVER 8-BIT DUAL-SUPPLY QFN24; Automotive Alternate_mfr_name: TEXAS INSTRUMENTS; Automotive Alternate_mfr_part_number: CAVC8T245QRHLRQ1; Chkd/date: VASANTHA/231216; Crtd /date: BAVISH/290411; Custom_Duty: 15%; Customs_HS_Code: 85423100; Distributor_name: DIGIKEY; Distributor_part_number: 296-17859-1-ND; Height: 1.00MM; Manufacturer: TEXAS INSTRUMENTS; Mfr_name: TEXAS INSTRUMENTS; Mfr_part_number: SN74AVC8T245RHLR; Mistral Part No: 143011040001-R; Package: QFN24; Part_type: ICS\TELECOM\TRANSCEIVER; Project: OMAPL1_PEC20; RoHS: RoHS; Temperature: -40°C+85°C; Tolerance: NA; Voltage: NA; Wattage: NA; Weight: NA; Datasheet: Y:\MIS_DATABASE\DATASHEETS\ICS\DIGITAL\BUSTRANSCEIVER\SN74AVC8T245.PDF
U243 = TCA6424ARGJR_QFN32: IC I2C I/O EXPANDER 24B UQFN32; Chkd/date: NAVEED/100715; Crtd /date: NAVEED/100914; Custom_Duty: 15%; Customs_HS_Code: 85423100; Distributor_name: DIGIKEY; Distributor_part_number: 296-27844-1-ND; Height: 0.60MM; Manufacturer: TEXAS INSTRUMENTS; Mfr_name: TEXAS INSTRUMENTS; Mistral Part No: 141014090009-R; Package: UQFN32; Part_type: ICS\DIGITAL\BUSTRANSCEIVER; Project: ZK_BIOMETRIC; RoHS: RoHS; Temperature: -40°C+85°C; Weight: NA; Datasheet: Y:\MIS_DATABASE\DATASHEETS\ICS\DIGITAL\BUSTRANSCEIVER\TCA6424AR.PDF
U244 U248 = SN74AVC4T245DGVR_TVSOP16: IC 4-BIT DUAL SUPPLY BUS TRANSCEIVER TVSOP16; Chkd/date: SUHAS/251010; Crtd /date: MAZHAR/201109; Custom_Duty: 15%; Customs_HS_Code: 85423100; Distributor_name: DIGIKEY; Distributor_part_number: 296-18054-1-ND; Height: 1.20MM; Manufacturer: TEXAS INSTRUMENTS; Mfr_name: TEXAS INSTRUMENTS; Mistral Part No: 141009110005-P; Package: TVSOP16; Part_type: ICS\DIGITAL\COMBINATIONAL; Project: GOLDEN-I; RoHS: Sb/ Br FREE; Temperature: -40°C+85°C; Datasheet: Y:\MIS_DATABASE\DATASHEETS\ICS\DIGITAL\BUSTRANSCEIVER\SN74AVC4T245.PDF
U253 = SN74LVC1G08DBVRE4_SOT23-5: IC SINGLE 2-INPUT POSITIVE AND GATE SOT23-5; Automotive Alternate_mfr_name: TEXAS INSTRUMENTS; Automotive Alternate_mfr_part_number: SN74LVC1G08QDBVRQ1; Chkd/date: SUHAS/221010; Crtd /date: USMAN/151008; Custom_Duty: 15%; Customs_HS_Code: 85423100; Distributor_name: DIGIKEY; Distributor_part_number: SN74LVC1G08DBVRE4-ND; Height: 1.45MM; Manufacturer: TEXAS INSTRUMENTS; Mfr_name: TEXAS INSTRUMENTS; Mistral Part No: 141009060026-R; Part_type: ICS\DIGITAL\GATES; Project: KHAN_MAIN; RoHS: Sb/ Br FREE; Temperature: -40°C+85°C; Datasheet: Y:\MIS_DATABASE\DATASHEETS\ICS\DIGITAL\GATES\SN74LVC1G08.PDF
J50 = CON_FLEX_40X1_FH12A-40S-0.5SH: CON FPC 40X1 0.50MM PITCH RT TOP SMD; Alternate Temperature: CON_FLEX40X1_FH12A_S_R_S_PMP take this footprint for PMP LCD BOARD/ROHS INFORMATION ADDED(BAVISH/270911)Mistral part# updated with -R.; Chkd/date: SHREESHAIL/201106; Crtd /date: MAZHAR/171106; Custom_Duty: 24%; Customs_HS_Code: 85369090; Distributor_name: DIGIKEY; Distributor_part_number: HFK40CT-ND; Height: 2.00MM; Manufacturer: HIROSE ELECTRIC EUROPE; Mfr_name: HIROSE ELECTRIC EUROPE; Mfr_part_number: FH12A-40S-0.5SH(55); Mistral Part No: 150009030176-R; Package: SMD; Part_type: CONNECTOR\FPC; Project: PMP LCD BOARD; Datasheet: Y:\MIS_DATABASE\DATASHEETS\CONNECTORS\FH12SERIES.PDF
Q1 = MOSFET_BSS138W: IC MOSFET N-CHANNEL 60V, SOT323; Chkd/date: SUHAS/191010; Crtd /date: MAZHAR/240907; Custom_Duty: 15%; Customs_HS_Code: 85423100; Height: 1.00MM; Manufacturer: INFINEON TECHNOLOGIES; Mfr_name: INFINEON TECHNOLOGIES; Mistral Part No: 142009030152-R; Package: SOT323; Part_type: ICS\POWER\MOSFET; Project: SMART VIEW_NVR; RoHS: RoHS; Temperature: -55°C+150°C; Voltage: 60V; Datasheet: Y:\MIS_DATABASE\DATASHEETS\DISCRETES\TRANSISTORS_FETS\BSS138W.PDF
R60-R63 = RESISTOR: RES 2.2K 1/16W 5% 0402; Chkd/date: VASANTHA/061216; Crtd /date: BAVISH/021210; Custom_Duty: 15%; Customs_HS_Code: 85332119; Distributor_name: DIGIKEY; Distributor_part_number: 311-2.2KJRCT-ND; Footprint Path: Y:\MIS_DATABASE\Library\ALTIUM_TOOL\PCB_FOOTPRINTS\Altium_Footprint_Lib.PcbLib; Height: 0.40MM; Library Path: Y:\MIS_DATABASE\Library\ALTIUM_TOOL\SCHEMATICS_PARTS\MS_DISCRETE_Library.schlib; Manufacturer: YAGEO AMERICA; Mfr_name: YAGEO AMERICA; Mfr_part_number: RC0402JR-072K2L; Mistral Part No: 110010120018-R; Package: 0402; Part_type: RESISTORS\FIXED; Project: TE4; RoHS: RoHS; Temperature: -55°C+155°C; Tolerance: 5%; Voltage: NA; Wattage: 1/16W; Weight: 0.65mg; Datasheet: Y:\MIS_DATABASE\DATASHEETS\RESISTORS\RCXXXXL-SER_MAR18.PDF
TP26 = TESTPOINT: TESTPOINT CIR 40 SMD; Chkd/date: MAZHAR/190505; Crtd /date: MAZHAR/190505; Distributor_name: NA; Distributor_part_number: NA; Footprint Path: Y:\MIS_DATABASE\Library\ALTIUM_TOOL\PCB_FOOTPRINTS\Altium_Footprint_Lib.PcbLib; Height: NA; Library Path: Y:\MIS_DATABASE\Library\ALTIUM_TOOL\SCHEMATICS_PARTS\MS_DISCRETE_Library.schlib; MECHANICAL 3D STEP FILE: NA; Manufacturer: LOCAL; Mfr_name: LOCAL; Mistral Part No: 130009030933; Package: SMD; Project: RAINIER-3; RoHS: NA; Temperature: NA; Tolerance: NA; Voltage: NA; Wattage: NA; Weight: NA; Datasheet: NA
U19 = SN74CBTLV3257PWR_TSSOP16: IC 1OF 2 FET MULTIPLEXER/DEMULTIPLEXER TSSOP16; Chkd/date: SUHAS/251010; Crtd /date: USMAN/110809; Custom_Duty: 15%; Customs_HS_Code: 85423100; Distributor_name: DIGIKEY; Distributor_part_number: 296-9138-1-ND; Height: 1.20MM; Manufacturer: TEXAS INSTRUMENTS; Mfr_name: TEXAS INSTRUMENTS; Mistral Part No: 141009080007-R; Package: TSSOP16; Part_type: ICS\DIGITAL\COMBINATIONAL; Project: BUG_BASE-II; RoHS: Sb/ Br FREE; Temperature: -40°C+85°C; Datasheet: Y:\MIS_DATABASE\DATASHEETS\ICS\DIGITAL\COMBINATIONAL\SN74CBTLV3257.PDF

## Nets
DGND: C55.1 C91.1 C93.2 C134.2 C136.2 C137.2 C138.2 C139.1 C140.2 C141.2 C142.2 C143.2 C144.2 C147.1 C148.2 C151.2 C152.2 C153.1 C157.2 C159.2 C668.1 C676.1 C681.2 C682.2 C685.2 C711.2 C712.2 C713.2 C902.1 C1056.2 C1064.2 C1097.2 C1117.2 C1118.2 C1131.1 C1134.2 C1161.2 J50.7 J50.16 J50.25 J50.34 J50.40 J50.41 J50.42 Q1.2(S) R64.1 R132.1 R431.1 R436.1 R442.1 R451.1 R455.1 R461.1 R468.1 R475.1 R484.1 R497.1 R503.1 R515.1 R530.1 R537.1 R549.1 R554.1 R857.2 R874.2 R881.1 R884.2 R890.2 R894.2 R897.1 R914.2 R915.2 R1132.1 R1184.1 TP179.1(TP) U19.8(GND) U20.1(GND) U183.2(GND) U187.23(GND) U187.26(GND) U187.52(GND) U187.64(GND) U187.65(GND) U220.3(GND) U233.11(GND1) U233.12(GND2) U233.13(GND3) U233.25(EP) U243.25(GND) U243.33(EP) U244.8(GND1) U244.9(GND2) U248.8(GND1) U248.9(GND2) U253.3(GND) ; also on sheet 11 12 13 14 15 16 17 18 20 21 22 23 24 25 26 27 28 29 30 31 32 33 34 35 36 37 38 39 40 41 42 43 44 45 46 47 48 49 50 51 52 53 54 55 56 57 58 59 60 64 65 66 67 68 69 70 71 72 73 76 77 78 79 81 82 83 84
VCC_1V2: C136.1 C142.1 C148.1 C151.1 C157.1 C682.1 FL63.2 U187.17(VCC) U187.33(VCC) U187.49(VCC) U187.59(VCC) U187.62(VCC) ; also on sheet 42 68
VCCA_1V2: C134.1 C137.1 C138.1 C140.1 C141.1 C152.1 C685.1 C711.1 C712.1 FL63.1 U187.3(VCCA) U187.14(VCCA) U187.18(VCCA) U187.31(VCCA) U187.36(VCCA) U187.41(VCCA) U187.43(VCCA) U187.48(VCCA)
BOOTBUF_ADDR: R1132.2 U243.26(ADDR)
BOOTMODEON: R1180.1 R1184.2 U233.22(~{OE}) U244.14(~{2OE}) U244.15(~{1OE}) U248.14(~{2OE}) U248.15(~{1OE})
BOOTMODEON_IN1: R1170.1 TP190.1(TP) U253.1(A)
BUF_1V8_BOOTMODE0: U248.13(1B1) ; also on sheet 16
BUF_1V8_BOOTMODE1: U248.12(1B2) ; also on sheet 16
BUF_1V8_BOOTMODE2: U248.11(2B1) ; also on sheet 16
BUF_1V8_BOOTMODE3: U248.10(2B2) ; also on sheet 16
BUF_3V3_BOOTMODE4: U244.13(1B1) ; also on sheet 18
BUF_3V3_BOOTMODE5: U244.12(1B2) ; also on sheet 18
BUF_3V3_BOOTMODE6: U244.11(2B1) ; also on sheet 18
BUF_3V3_BOOTMODE7: U244.10(2B2) ; also on sheet 18
BUF_MCU_BOOTMODE2: U233.21(B1) ; also on sheet 18
BUF_MCU_BOOTMODE3: U233.20(B2) ; also on sheet 18
BUF_MCU_BOOTMODE4: U233.19(B3) ; also on sheet 18
BUF_MCU_BOOTMODE5: U233.18(B4) ; also on sheet 18
BUF_MCU_BOOTMODE6: U233.17(B5) ; also on sheet 18
BUF_MCU_BOOTMODE7: U233.16(B6) ; also on sheet 18
BUF_MCU_BOOTMODE8: U233.15(B7) ; also on sheet 18
BUF_MCU_BOOTMODE9: U233.14(B8) ; also on sheet 18
C_DP1_AUX_N: C664.1 U187.35(AUXN)
C_DP1_AUX_P: C665.1 U187.34(AUXP)
C_DP1_TX0_N: C662.1 U187.38(ML0N)
C_DP1_TX0_P: C663.1 U187.37(ML0P)
C_DP1_TX1_N: C660.1 U187.40(ML1N)
C_DP1_TX1_P: C661.1 U187.39(ML1P)
C_DP1_TX2_N: C658.1 U187.45(ML2N)
C_DP1_TX2_P: C659.1 U187.44(ML2P)
C_DP1_TX3_N: C656.1 U187.47(ML3N)
C_DP1_TX3_P: C657.1 U187.46(ML3P)
CTRL_PM_I2C_OE#: Q1.1(G) R132.2 ; also on sheet 38
DIR1: R1144.1 U244.2(1DIR) U244.3(2DIR) U248.2(1DIR) U248.3(2DIR)
DIR2: R1109.1 U233.2(DIR)
DP1_AUX_N: C664.2 ; also on sheet 57
DP1_AUX_P: C665.2 ; also on sheet 57
DP1_HPD_BUF: R776.2 ; also on sheet 57
DP1_TX0_N: C662.2 ; also on sheet 57
DP1_TX0_P: C663.2 ; also on sheet 57
DP1_TX1_N: C660.2 ; also on sheet 57
DP1_TX1_P: C661.2 ; also on sheet 57
DP1_TX2_N: C658.2 ; also on sheet 57
DP1_TX2_P: C659.2 ; also on sheet 57
DP1_TX3_N: C656.2 ; also on sheet 57
DP1_TX3_P: C657.2 ; also on sheet 57
DSI0_TX0_N: U187.20(DA0N) ; also on sheet 11
DSI0_TX0_P: U187.19(DA0P) ; also on sheet 11
DSI0_TX1_N: U187.22(DA1N) ; also on sheet 11
DSI0_TX1_P: U187.21(DA1P) ; also on sheet 11
DSI0_TX2_N: U187.28(DA2N) ; also on sheet 11
DSI0_TX2_P: U187.27(DA2P) ; also on sheet 11
DSI0_TX3_N: U187.30(DA3N) ; also on sheet 11
DSI0_TX3_P: U187.29(DA3P) ; also on sheet 11
DSI0_TXCLK_N: U187.25(DACN) ; also on sheet 11
DSI0_TXCLK_P: U187.24(DACP) ; also on sheet 11
eDP_ADDR: R915.1 U187.1(ADDR)
eDP_GPIO1: R893.2 R894.1 U187.58(GPIO1)
eDP_GPIO2: R883.2 R884.1 U187.56(GPIO2)
eDP_GPIO3: R864.2 R874.1 U187.54(GPIO3)
eDP_GPIO4: R889.2 R890.1 U187.57(GPIO4)
eDP_I2C4_SCL: R113.2 U20.3(SCL1) U187.15(SCL)
eDP_I2C4_SDA: R112.2 U20.4(SDA1) U187.16(SDA)
eDP_IRQ: R999.2 U187.61(IRQ) U220.2(A)
eDP_REFCLK: R857.1 R858.2 TP258.1(TP) U187.51(REFCLK)
eDP_TEST1: R897.2 U187.60(TEST1)
eDP_TEST2: R880.1 R881.2 U187.55(TEST2)
eDP_TEST3: C668.2 U187.50(TEST3)
GPIO_eDP_ENABLE: R913.1 ; also on sheet 38
I2C1_SCL: R95.1 ; also on sheet 20
I2C1_SDA: R91.1 ; also on sheet 20
I2C4_SCL: U20.6(SCL2) ; also on sheet 20 38
I2C4_SDA: U20.5(SDA2) ; also on sheet 20 38
MCU_BOOTMODE02: R475.2 SW7.1 U233.3(A1) U243.1(P00)
MCU_BOOTMODE03: R468.2 SW7.2 U233.4(A2) U243.2(P01)
MCU_BOOTMODE04: R461.2 SW7.3 U233.5(A3) U243.3(P02)
MCU_BOOTMODE05: R455.2 SW7.4 U233.6(A4) U243.4(P03)
MCU_BOOTMODE06: R451.2 SW7.5 U233.7(A5) U243.5(P04)
MCU_BOOTMODE07: R442.2 SW7.6 U233.8(A6) U243.6(P05)
MCU_BOOTMODE08: R436.2 SW7.7 U233.9(A7) U243.7(P06)
MCU_BOOTMODE09: R431.2 SW7.8 U233.10(A8) U243.8(P07)
MCU_PERIPH_RSTz: R1181.1 ; also on sheet 17 18 37 44
PM1_SCL: J50.36 R63.2 U19.2(1B1) ; also on sheet 47 73 76 78
PM1_SDA: J50.38 R61.2 U19.5(2B1) ; also on sheet 47 73 76 78
PM2_SCL: J50.37 R62.2 U19.3(1B2) U243.29(SCL) ; also on sheet 47 73 77 79
PM2_SDA: J50.39 R60.2 U19.6(2B2) U243.30(SDA) ; also on sheet 47 73 77 79
PM_I2C_OE#: Q1.3(D) R116.2 U19.15(~{OE})
PM_I2C_SEL: R64.2 U19.1(S) ; also on sheet 18
R_DP1_HPD: R776.1 U187.32(HPD)
RESETSTATZ: R1172.1 ; also on sheet 18 30 37
SoC_eDP_IRQ: R1017.2 U220.4(Y) ; also on sheet 20
SOC_I2C1_SCL_R: R95.2 U19.4(1A)
SOC_I2C1_SDA_R: R91.2 U19.7(2A)
SOC_PORZ_OUT: R1185.1 ; also on sheet 18 30 32 37 43 51 56 59 60 69
SYS_BOOTMODE0: R554.2 SW11.1 U243.9(P10) U248.4(1A1)
SYS_BOOTMODE1: R549.2 SW11.2 U243.10(P11) U248.5(1A2)
SYS_BOOTMODE2: R537.2 SW11.3 U243.11(P12) U248.6(2A1)
SYS_BOOTMODE3: R530.2 SW11.4 U243.12(P13) U248.7(2A2)
SYS_BOOTMODE4: R515.2 SW11.5 U243.13(P14) U244.4(1A1)
SYS_BOOTMODE5: R503.2 SW11.6 U243.14(P15) U244.5(1A2)
SYS_BOOTMODE6: R497.2 SW11.7 U243.15(P16) U244.6(2A1)
SYS_BOOTMODE7: R484.2 SW11.8 U243.16(P17) U244.7(2A2)
SYSBOOT_BUF_ENz: R1172.2 R1181.2 R1185.2 U253.2(B)
TA_BM_IOEXP_RSTn: J50.33 R137.1 U243.28(~{RESET}) ; also on sheet 47
TA_BOOTMODE_CNTL#: J50.32 R142.1 TP26.1(TP) ; also on sheet 47
TA_PORZn: J50.27 R827.1 ; also on sheet 36 47
TA_POWERDOWNz: J50.26 ; also on sheet 35 47
TA_RESETz: J50.28 R826.1 ; also on sheet 36 47
TA_SOC_INT1z: J50.30 R144.1 ; also on sheet 35 47
TA_SOC_INT2z: J50.31 R143.1 ; also on sheet 35 47
TCA6424_EXP_INT: R1135.1 U243.32(~{INT})
VPLL_1V8_eDP: C139.2 FL7.2 U187.42(VPLL)
VREF2_eDP_I2C: C55.2 R71.2 U20.7(VREF2) U20.8(EN)
VSYS_3V3: C93.1 C143.1 C144.1 C1064.1 C1097.1 C1117.1 C1131.2 C1161.1 J50.1 J50.2 J50.3 R60.1 R61.1 R62.1 R63.1 R116.1 R137.2 R142.2 R143.2 R144.2 R430.1 R435.1 R441.1 R450.1 R454.1 R460.1 R467.1 R474.1 R483.1 R496.1 R502.1 R514.1 R529.1 R536.1 R548.1 R553.1 R826.2 R827.2 R1109.2 R1135.2 R1144.2 R1170.2 U19.16(VCC) U233.1(VCCA) U243.27(VCCP) U243.31(VCC) U244.1(VCCA) U248.1(VCCA) U253.5(VCC) ; also on sheet 22 23 35 36 40 47 49 65 66 67 68 69 73 75 76 77 78 79
VSYS_IO_1V8: C91.2 C147.2 C153.2 C159.1 C676.2 C902.2 FL7.1 R112.1 R113.1 R864.1 R880.2 R883.1 R889.1 R893.1 R999.1 U20.2(VREF1) U183.1(STANDBY) U183.4(VDD) U187.53(VCCIO) U187.63(VCCIO) U220.5(VCC) ; also on sheet 30 32 33 34 37 38 41 42 65 75
VSYS_IO_3V3: R71.1 R1017.1 ; also on sheet 18 20 22 24 29 30 31 32 33 35 36 37 38 40 41 42 43 45 46 48 50 51 53 56 57 58 59 60 65 66 68 75 81 82
VSYS_MCUIO_1V8: C1134.1 U248.16(VCCB) ; also on sheet 17 21 37 39 53 65 75
VSYS_MCUIO_3V3: C1056.1 C1118.1 U233.23(VCCB1) U233.24(VCCB2) U244.16(VCCB) ; also on sheet 16 17 18 21 22 23 35 36 43 44 48 49 55 65 68 75
N22857883: R454.2 SW7.13
N22857884: R460.2 SW7.14
N22857885: R467.2 SW7.15
N22857886: R474.2 SW7.16
N22857888: R435.2 SW7.10
N22857889: R441.2 SW7.11
N22857890: R450.2 SW7.12
N23037276: R529.2 SW11.13
N23037278: R536.2 SW11.14
N23037280: R548.2 SW11.15
N23037282: R553.2 SW11.16
N23037308: R483.2 SW11.9
N23037310: R496.2 SW11.10
N23037312: R502.2 SW11.11
N23037314: R514.2 SW11.12
N24353848: R1180.2 U253.4(Y)
N26873381: R430.2 SW7.9
N32706667: C681.1 R858.1 U183.3(OUTPUT)
N32707436: C713.1 R913.2 R914.1 U187.2(EN)

Not connected (* = marked no-connect by the designer): J50 4* 5* 6* 8* 9* 10* 11* 12* 13* 14* 15* 17* 18* 19* 20* 21* 22* 23* 24* 29* 35*; U19 9(3A) 10(3B2) 11(3B1) 12(4A) 13(4B2) 14(4B1); U187 4(DB0P)* 5(DB0N)* 6(DB1P)* 7(DB1N)* 8(DBCP)* 9(DBCN)* 10(DB2P)* 11(DB2N)* 12(DB3P)* 13(DB3N)*; U220 1(NC)*; U243 17(P20)* 18(P21)* 19(P22)* 20(P23)* 21(P24)* 22(P25)* 23(P26)* 24(P27)*

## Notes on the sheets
sheet 61
- DSI to eDP Bridge
- I2C SLAVE ADDRESS: 0x2C
- GPIO[3:1] is set as 3’b001 for 19.2MHz External Refclk
sheet 62
- BOOT MODE BUFFER & SWITCHES
- SWITCH ON  =  LOGIC 1
  SWITCH OFF =  LOGIC 0
- I2C ADDRESS: 0x22
- BOOTMODE Control Buffers
- DIR = H: A -> B
- TP1
- TP2
- Place TP1 and TP2 with 100mils
  spacing to insert external jumper
- SWITCH ON  =  LOGIC 1
  SWITCH OFF =  LOGIC 0
- DIR = H: A -> B
- BOOTMODE Control
  from Test
  Automation HDR
- TA_BM_IOEXP_RSTn
- SOC_PORZ_OUT
- HIGH
- LOW
- Enabled
- HIGH
- HIGH
- Disabled
sheet 63
- TEST AUTOMATION HEADER
- AUTOMATION INTERFACE
- ALL SIGNALS SHOULD BE
  REFERENCED TO EVM_3V3
- Cable : Parlex-050R40-76B, .5mm 3"
- Silkscreen:"AUTOMATION CONNECTOR"
- PM_I2C HAVE ON BOARD PULLUPS.
  AUTOMATION SHOULD BE WEAK
  ~20K OR HIGHER.
- I2C SWITCH
- TEST AUTOMATION  GPIO MAPPING
- Internal/
  External
  PU/PD states
- Direction WRT CTRL
- SIGNAL NAME
- DESCRIPTION
- TA_POWERDOWN
  TA_PORZn
  TA_RESETz
  TA_SOC_INT1z
  TA_SOC_INT2z
  TA_BM_IOEXP_RSTn
- Used to Power down the system
  MCU & Main SoC domain Power ON Reset
  SoC Warmreset
  Interrupt to SOC
  Interrupt to SOC
  Used to Reset the Bootmode IO Expander
- OUTPUT
- External Pullup
- From SOC GPIO
- OUTPUT
- External Pullup
- OUTPUT
- External Pullup
- OUTPUT
- External Pullup
- OUTPUT
- External Pullup
- From GPIO EXPANDER
- External Pullup
- OUTPUT
